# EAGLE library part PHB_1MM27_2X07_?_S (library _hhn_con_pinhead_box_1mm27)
Pin Header Box-Type, 1.27mm/0.5"/50mil Pitch, 2x07 Circuits, single gates in schematic Note: see library description for an important note about THT-version
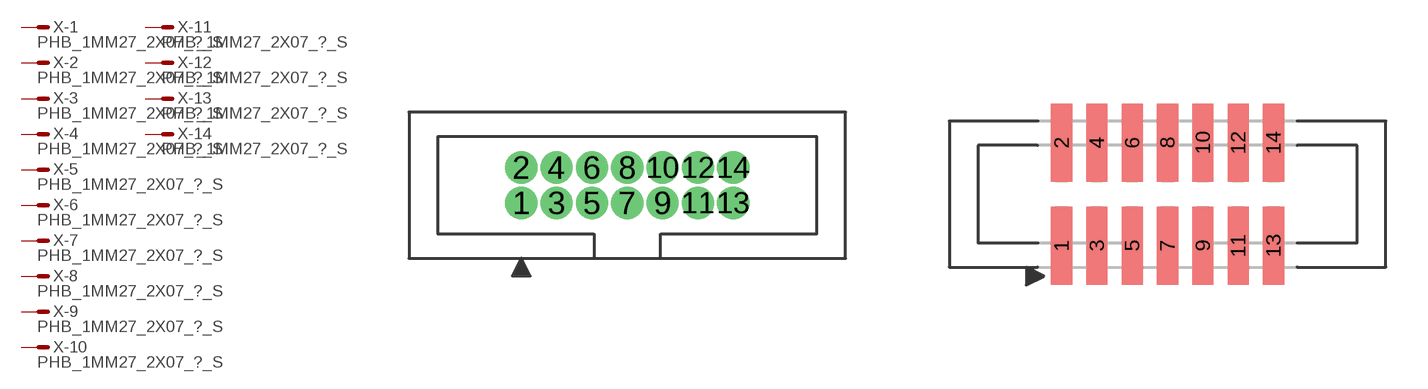
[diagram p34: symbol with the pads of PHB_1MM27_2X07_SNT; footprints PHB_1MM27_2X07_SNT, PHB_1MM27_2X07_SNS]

Designator prefix X; gates -1=M -2=M -3=M -4=M -5=M -6=M -7=M -8=M -9=M -10=M -11=M -12=M -13=M -14=M

## PHB_1MM27_2X07_SNT_S  [PHB_1MM27_2X07_SNT]
1  -1:S  pas
2  -2:S  pas
3  -3:S  pas
4  -4:S  pas
5  -5:S  pas
6  -6:S  pas
7  -7:S  pas
8  -8:S  pas
9  -9:S  pas
10  -10:S  pas
11  -11:S  pas
12  -12:S  pas
13  -13:S  pas
14  -14:S  pas

## PHB_1MM27_2X07_SNS_S  [PHB_1MM27_2X07_SNS]
Pads as for PHB_1MM27_2X07_SNT

## Footprint PHB_1MM27_2X07_SNT (pad centres in mm)
Pin Header Box-Type, 1.27mm Pitch, 2x07 circuits, Straight, No Locking, THT Important Note: Diameter in this lbr is set to a specific value (NOT 'auto' = 0), this is ignored by actual eagle versions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
drill 0.65 pad 1 round: 1 -3.81,-0.635; 2 -3.81,0.635; 3 -2.54,-0.635; 4 -2.54,0.635; 5 -1.27,-0.635; 6 -1.27,0.635; 7 0,-0.635; 8 0,0.635; 9 1.27,-0.635; 10 1.27,0.635; 11 2.54,-0.635; 12 2.54,0.635; 13 3.81,-0.635; 14 3.81,0.635

## Footprint PHB_1MM27_2X07_SNS (pad centres in mm)
Pin Header Box-Type, 1.27mm Pitch, 2x07 circuits, Straight, No Locking, SMT
smd 0.76 x 2.8: 1 -3.81,-1.85; 2 -3.81,1.85; 3 -2.54,-1.85; 4 -2.54,1.85; 5 -1.27,-1.85; 6 -1.27,1.85; 7 0,-1.85; 8 0,1.85; 9 1.27,-1.85; 10 1.27,1.85; 11 2.54,-1.85; 12 2.54,1.85; 13 3.81,-1.85; 14 3.81,1.85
